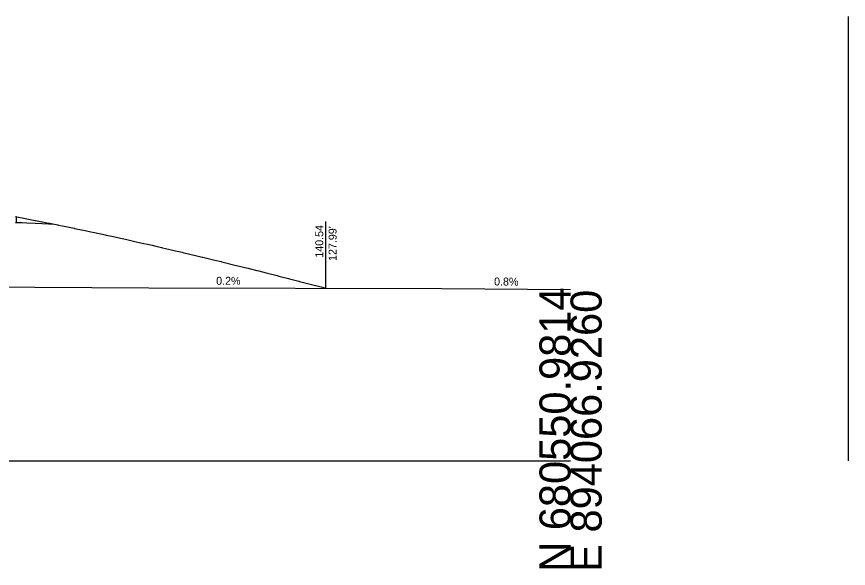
# Model space of a CAD drawing. Extents: x -26 to 4403, y -13 to 9578.
# Drawn here: x 1350.1 to 1425, y 7490.3 to 7540 of the extents above; entities that cross this region are included whole.
import ezdxf

# ---------------------------------------------------------------- set-up
doc = ezdxf.new("R2010")
doc.units = 0
for name, color, linetype in [('DTM_X_GROUND', 7, 'Continuous'), ('X_PROFILES_1', 7, 'Continuous'), ('XS_CELL', 7, 'Continuous'), ('XS_P_DR_GRAVEL', 7, 'Continuous'), ('XS_P_DRAINAGE', 7, 'Continuous'), ('XS_P_GROUND', 7, 'Continuous'), ('XS_P_TX_CLEARZONE', 7, 'Continuous'), ('XS_P_TX_FS_BS', 7, 'Continuous')]:
    doc.layers.add(name, color=color, linetype=linetype)

msp = doc.modelspace()

# ---------------------------------------------------------------- linework, layer by layer
at = {"layer": 'DTM_X_GROUND'}
msp.add_lwpolyline([(1304.806, 7515.777), (1309.035, 7515.784), (1309.106, 7515.785), (1310.099, 7515.786), (1311.498, 7515.789), (1331.242, 7515.749), (1362.053, 7515.566), (1388.429, 7515.524), (1400, 7515.43)], dxfattribs=at)
at = {"layer": 'XS_CELL'}
msp.add_line((1250, 7500), (1400, 7500), dxfattribs=at)
at = {"layer": 'XS_P_DR_GRAVEL'}
for points in [[(1350.05, 7521.468), (1350.15, 7521.464), (1350.15, 7521.964), (1350.05, 7521.968)], [(1350.15, 7521.464), (1350.634, 7521.444), (1351.055, 7521.428), (1351.816, 7521.397), (1352.439, 7521.373), (1353.024, 7521.349), (1353.383, 7521.334)]]:
    msp.add_lwpolyline(points, dxfattribs=at)
at = {"layer": 'XS_P_DRAINAGE'}
msp.add_line((1425, 7500), (1425, 7540), dxfattribs=at)
at = {"layer": 'XS_P_GROUND'}
msp.add_lwpolyline([(1350.15, 7521.964), (1350.634, 7521.872), (1350.641, 7521.87), (1351.055, 7521.792), (1351.08, 7521.787), (1351.816, 7521.645), (1351.854, 7521.637), (1352.439, 7521.523), (1352.488, 7521.513), (1353.024, 7521.407), (1353.112, 7521.389), (1353.859, 7521.239), (1353.913, 7521.228), (1354.259, 7521.158), (1354.422, 7521.125), (1355.316, 7520.94), (1355.355, 7520.932), (1355.523, 7520.899), (1355.651, 7520.872), (1356.166, 7520.763), (1356.311, 7520.733), (1356.815, 7520.625), (1357.153, 7520.554), (1358.144, 7520.339), (1358.207, 7520.326), (1358.358, 7520.294), (1358.716, 7520.216), (1359.506, 7520.041), (1359.66, 7520.008), (1359.947, 7519.945), (1360.303, 7519.866), (1360.905, 7519.73), (1361.181, 7519.669), (1361.588, 7519.577), (1361.913, 7519.503), (1362.343, 7519.405), (1362.68, 7519.328), (1363.077, 7519.236), (1363.175, 7519.213), (1363.282, 7519.188), (1363.548, 7519.128), (1363.823, 7519.064), (1364.458, 7518.916), (1365.036, 7518.779), (1365.208, 7518.739), (1365.347, 7518.707), (1366.232, 7518.496), (1366.852, 7518.346), (1366.878, 7518.341), (1366.919, 7518.331), (1367.976, 7518.075), (1368.542, 7517.935), (1368.605, 7517.92), (1368.737, 7517.889), (1369.8, 7517.628), (1370.219, 7517.523), (1370.575, 7517.436), (1370.696, 7517.406), (1370.987, 7517.334), (1371.079, 7517.31), (1371.769, 7517.138), (1371.955, 7517.091), (1372.591, 7516.931), (1372.735, 7516.895), (1373.601, 7516.675), (1373.752, 7516.636), (1374.601, 7516.418), (1374.71, 7516.389), (1375.542, 7516.177), (1375.617, 7516.158), (1377.032, 7515.79), (1377.079, 7515.778), (1377.547, 7515.657), (1377.554, 7515.655), (1377.986, 7515.541)], dxfattribs=at)
at = {"layer": 'XS_P_TX_CLEARZONE'}
msp.add_line((1377.986, 7515.541), (1377.986, 7521.541), dxfattribs=at)

# ---------------------------------------------------------------- texts
at = {"layer": 'X_PROFILES_1'}
msp.add_text('X', height=0.12, dxfattribs=at).set_placement((1377.947, 7515.481))
at = {"layer": 'XS_CELL'}
for s, p in [('N 680550.9814', (1400, 7490)), ('E 894066.9260', (1402.8, 7490))]:
    msp.add_text(s, height=2.8, rotation=90, dxfattribs=at).set_placement(p)
at = {"layer": 'XS_P_TX_CLEARZONE'}
for s, p in [('140.54', (1377.746, 7518.288)), ("127.99'", (1378.946, 7517.993))]:
    msp.add_text(s, height=0.72, rotation=90, dxfattribs=at).set_placement(p)
at = {"layer": 'XS_P_TX_FS_BS'}
for s, rotation, p in [('0.2%', 359.90926, (1368.105, 7515.847)), ('0.8%', 359.53529, (1393.115, 7515.786)), ('0.8%', 359.53529, (1393.115, 7515.786))]:
    msp.add_text(s, height=0.72, rotation=rotation, dxfattribs=at).set_placement(p)

doc.saveas('drawing.dxf')
